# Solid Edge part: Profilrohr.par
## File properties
Username: ahadarics
Dokumentum tartalom típus: 0
Author: ahadarics
Last saved by: ahadarics
Revision: 81
Sűrűség: 0,000 kg/m^3
Pontosság: 0,990
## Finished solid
Body 1: solid body, 6 faces, 6 edges, 0 vertices.
  Faces by surface: cone 2, cylinder 2, plane 2
  Edges by curve: circle 6
Bounding box of the edges (mm): 21.270 x 21.270 x 157.000, from (-10.635, -10.635, -136) to (10.635, 10.635, 21).
Cylindrical faces by radius (mm): R10 x1, R10.635 x1
Conical faces (half-angle, radius in mm at the cone's reference point): 15 deg R10.067 x2
Planar faces by outward normal: +z 1, -z 1
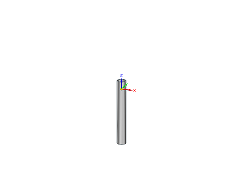
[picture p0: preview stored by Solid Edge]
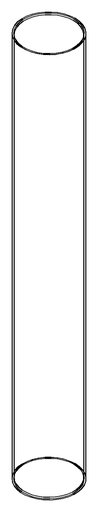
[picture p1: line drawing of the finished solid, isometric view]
